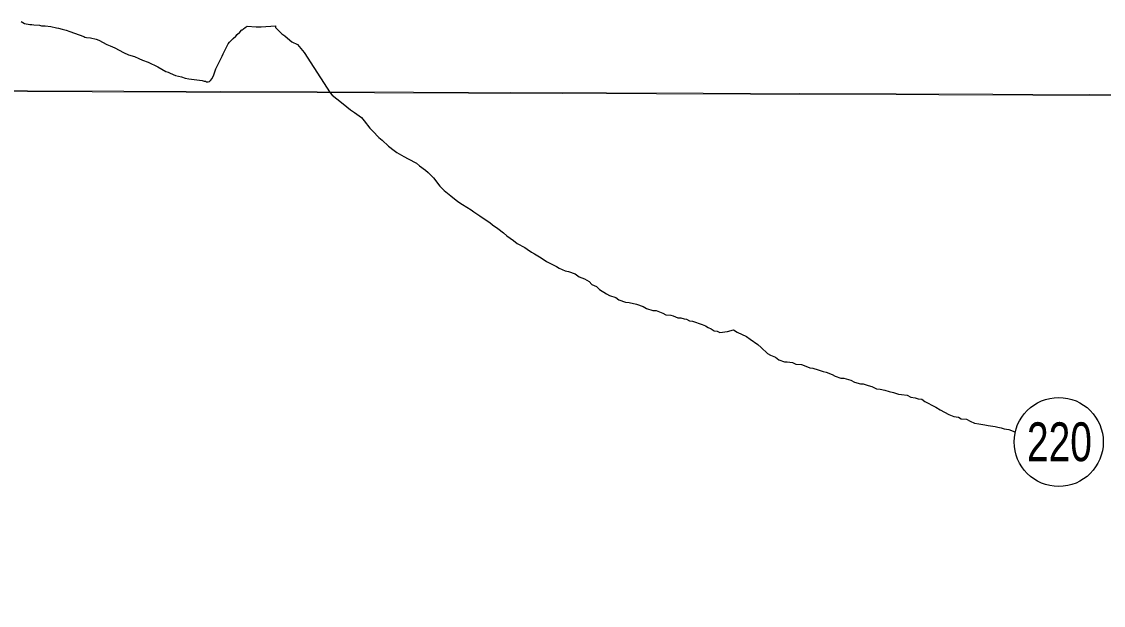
# Model space of a CAD drawing. Extents: x 553962 to 842807, y 8883888 to 9032388.
# Drawn here: x 593608 to 595557, y 8909015 to 8910067 of the extents above; entities that cross this region are included whole.
import ezdxf
from ezdxf.enums import TextEntityAlignment as Align

# ---------------------------------------------------------------- set-up
doc = ezdxf.new("R2010")
doc.units = 0
doc.header["$LTSCALE"] = 200
doc.layers.add('6', color=7, linetype='Continuous', lineweight=13)

msp = doc.modelspace()

# ---------------------------------------------------------------- linework, layer by layer
at = {"layer": '6'}
msp.add_line((574653.9, 8910009.3), (626625.7, 8909822.1), dxfattribs=at)
at = {"layer": '6', "lineweight": 25}
for points in [[(593606.6, 8910067.2), (593612.7, 8910063.9), (593622.6, 8910062.1), (593626.3, 8910061.8), (593629.6, 8910061.2), (593640, 8910060.7), (593643.5, 8910059.9), (593650.2, 8910059.4), (593660.1, 8910058.2), (593670.6, 8910056), (593673.9, 8910055.6), (593680.7, 8910053.3), (593687.8, 8910051.7), (593694.5, 8910049.6), (593711.2, 8910043.1), (593719.9, 8910040.3), (593721.8, 8910039.2), (593724.7, 8910038.3), (593732, 8910037.7), (593742.2, 8910035.3), (593746.6, 8910033.6), (593761, 8910026.2), (593767.3, 8910023.6), (593775.5, 8910019.8), (593791.3, 8910011.7), (593800.5, 8910007.3), (593810.8, 8910004.2), (593819.1, 8910001), (593825.5, 8909998), (593835.5, 8909994), (593853, 8909985.5), (593867.8, 8909977.5), (593872, 8909976.1), (593875.5, 8909974.1), (593885.1, 8909970.1), (593895.5, 8909967.6), (593902.5, 8909965.3), (593909.1, 8909963.8), (593932.8, 8909961), (593936.4, 8909960), (593939.1, 8909959.7), (593941.1, 8909958.7), (593943.7, 8909958.9), (593946.2, 8909959.5), (593948.1, 8909960.9), (593951.3, 8909964.8), (593954, 8909971.3), (593957.5, 8909981.8), (593969.1, 8910005.1), (593970.9, 8910009.4), (593979.7, 8910026.9), (593982.4, 8910030.4), (593988.7, 8910036.9), (593993.8, 8910041.2), (593996.3, 8910044), (594000.9, 8910048.2), (594004.6, 8910052.2), (594005.8, 8910052.6), (594007.4, 8910054.3), (594010.6, 8910056.6)], [(594010.6, 8910056.6), (594013.9, 8910058.9), (594030.2, 8910058), (594039.3, 8910057.8), (594065.1, 8910059.8)], [(594065.1, 8910059.8), (594065.3, 8910056.9), (594071.5, 8910049.8), (594076.6, 8910045.4), (594082, 8910041.4), (594090.9, 8910033.6), (594094.4, 8910030.9), (594104.6, 8910026.1), (594117, 8910011.3), (594163.5, 8909939)], [(594163.5, 8909939), (594167.3, 8909934.5), (594175.7, 8909928), (594187.2, 8909918.9), (594200.6, 8909908.3), (594207.6, 8909903.2), (594220, 8909894.1), (594224.9, 8909888.6), (594235.3, 8909875), (594240.8, 8909869.4), (594251.7, 8909858.4), (594257.7, 8909853.3), (594268.6, 8909842.7), (594279.1, 8909834.7), (594284, 8909831.1), (594296.5, 8909824), (594304.5, 8909820), (594319.4, 8909811.8), (594324.9, 8909807.3), (594335.3, 8909799.2), (594340.3, 8909795.2), (594350.2, 8909785.6)], [(594350.2, 8909785.6), (594361.6, 8909770.5), (594369.1, 8909762.9), (594381, 8909752.9), (594393.9, 8909742.8), (594402.4, 8909737.7), (594417.8, 8909728.1), (594422.8, 8909724), (594433.7, 8909717), (594439.7, 8909712.9), (594451.2, 8909704.8), (594456.1, 8909700.8), (594465.6, 8909694.2), (594476, 8909686.1), (594482, 8909681.1), (594493.9, 8909672.5), (594500.9, 8909667.4), (594514.3, 8909659.8), (594518.8, 8909656.8), (594526.8, 8909651.2), (594532.2, 8909648.2), (594543.7, 8909641.1), (594553.7, 8909634.6), (594559.6, 8909631.5), (594571.6, 8909625.9), (594576.6, 8909622.9), (594587.5, 8909617.8), (594593, 8909616.8), (594605.5, 8909612.2), (594612.5, 8909607.1), (594622, 8909603.6), (594630.4, 8909598.5), (594635.4, 8909593.4), (594643.8, 8909589.4), (594649.3, 8909584.3), (594661.8, 8909576.2), (594667.2, 8909573.2), (594678.7, 8909569.6), (594684.2, 8909565.6), (594695.7, 8909561.5), (594702.7, 8909561), (594715.6, 8909557.9), (594727.6, 8909553.8), (594733.6, 8909549.7), (594745.1, 8909546.2), (594751.1, 8909546.1), (594763, 8909541.5), (594768.5, 8909538.5), (594777.5, 8909537.9), (594782, 8909536.4), (594790, 8909533.3), (594795.5, 8909532.8), (594801.5, 8909531.3), (594806, 8909530.7), (594811.5, 8909527.7), (594816.5, 8909527.2), (594822.4, 8909525.1), (594828.9, 8909523.1), (594833.9, 8909521), (594840.4, 8909518.5), (594844.9, 8909515.5), (594850.4, 8909513.4), (594855.8, 8909509.4), (594861.3, 8909508.8), (594865.8, 8909506.8), (594879.8, 8909508.2)], [(594879.8, 8909508.2), (594890.9, 8909511.2), (594897.3, 8909507.1), (594913.8, 8909499.5), (594920.8, 8909494.9), (594934.7, 8909484.8), (594940.7, 8909479.3), (594952.1, 8909468.7), (594957.1, 8909465.7), (594966.5, 8909462.1), (594972.5, 8909457.5), (594982.5, 8909454), (594987.5, 8909453.9), (594997, 8909452.4), (595003, 8909449.3), (595013.4, 8909448.8), (595017.9, 8909447.2), (595027.9, 8909443.2), (595033.4, 8909442.6), (595043.4, 8909439.5), (595052.4, 8909436.5), (595057.4, 8909435.4), (595068.3, 8909430.9), (595073.8, 8909427.8), (595084.3, 8909424.2), (595089.3, 8909424.2), (595101.8, 8909420.6), (595108.8, 8909417.1), (595119.7, 8909414), (595124.2, 8909414), (595133.2, 8909410.9), (595140.2, 8909409.4), (595148.2, 8909405.3), (595155.2, 8909404.2), (595163.2, 8909402.7), (595171.2, 8909400.1), (595179.1, 8909398.6), (595188.1, 8909395.5), (595193.1, 8909395), (595203.6, 8909393.4), (595210.1, 8909389.9), (595218.1, 8909388.8), (595223.6, 8909387.3), (595230.1, 8909386.2), (595235.5, 8909382.2), (595241.5, 8909379.2), (595248, 8909375.6), (595255, 8909372.1), (595262.9, 8909367), (595270.9, 8909362.9), (595278.9, 8909358.9), (595287.8, 8909355.3), (595296.3, 8909354.2), (595300.8, 8909350.7), (595310.3, 8909350.2), (595317.3, 8909346.6), (595324.8, 8909343.1), (595332.8, 8909342), (595343.3, 8909340.4), (595349.8, 8909338.9), (595362.2, 8909337.3), (595366.7, 8909335.8), (595373.2, 8909334.7), (595378.2, 8909333.2), (595386.7, 8909331.6), (595397.5, 8909327.7)]]:
    msp.add_lwpolyline(points, dxfattribs=at)
at = {"layer": '6'}
msp.add_lwpolyline([(596575.8, 8909932.4), (585614.8, 8909969.8), (585583.8, 8898914.4), (596544.8, 8898874.9)], close=True, dxfattribs=at)
at = {"layer": '6', "lineweight": 25}
msp.add_circle((595476.7, 8909309.2), 80.3, dxfattribs=at)

# ---------------------------------------------------------------- texts
at = {"layer": '6', "width": 0.75}
msp.add_text('220', height=70, dxfattribs=at).set_placement((595478, 8909274.6), align=Align.CENTER)

doc.saveas('drawing.dxf')
